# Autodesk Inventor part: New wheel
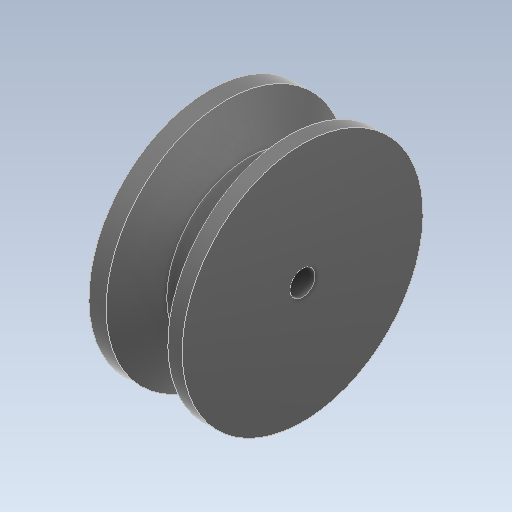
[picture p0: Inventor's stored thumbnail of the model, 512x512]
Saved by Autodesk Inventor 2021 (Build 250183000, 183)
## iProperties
Created: 2021-07
Part Number: New wheel
Material: Acetal Resin, Black
Document SubType Name: Sheet Metal
Designer: user
Density: 1.425 g/cm^3
Sheet Metal Rule: Default_mm
Appearance: Smooth - Black
Author: user
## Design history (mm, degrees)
sketch "Sketch1"
  geometry: L1 (0, 0)-(0, 1.5); L2 (0, 1.5)-(-0.178, 1.5); L3 (-0.178, 1.5)-(-0.482, 1.009); L4 (-0.482, 1.009)-(-0.448, 0); L5 (-0.448, 0)-(0, 0); L6 (-0.178, 1.5)-(-0.178, 0); L7 (-0.482, 1.009)-(0, 1.009); L8 (-0.482, 1.009)-(-0.682, 1.009); L9 (-0.682, 1.009)-(-0.966, 1.009); L10 (-0.966, 1.009)-(-1.161, 1.009); L11 (-1.161, 1.009)-(-1.161, 1.5); L12 (-1.161, 1.5)-(-0.946, 1.5); L13 (-0.946, 1.5)-(-0.946, 1.009); L14 (-0.946, 1.5)-(-0.682, 1.009); L15 (-1.161, 1.009)-(-1.161, 0); L16 (-1.161, 0)-(-0.946, 0); L17 (-0.946, 0)-(-0.946, 1.009); L18 (-0.682, 1.009)-(-0.682, 0); L19 (-0.682, 0)-(-0.946, 0); L20 (-0.682, 0)-(-0.448, 0); L21 (-0.682, 1.009)-(-0.482, 1.009)
  constraints: 42 end point, 8 perpendicular, 7 point on line, 4 horizontal, 2 vertical, 1 parallel
  dimensions: "d0" = 1.5 distance of L1.start L1.end; "d1" = 0.2 distance of L3.end L8.end
revolve "Revolution1" sketch "Sketch1" stored, may be unused: angle "d2" = 90 deg
sketch "Sketch2"
  geometry: C1 r 0.155 at (0, 0); 1 further point
  constraints: 1 centre point, 1 coincident
  dimensions: "d3" = 0.31 diameter of C1
cut "Cut1" sketch "Sketch2" dims "d5" = 0.5 (= Thickness), "d6" = 0
body "Solid1"
other parameters: "Thickness" = 0.5, "BendRadius" = 0.5 (= Thickness), "BendReliefWidth" = 0.5 (= Thickness), "BendReliefDepth" = 0.25 (= 0.5 x Thickness), "CornerReliefSize" = 2 (= 4 x Thickness), "SeamGap" = 0.01, "MinimumRemnant" = 1 (= 2 x Thickness), "TransitionRadius" = 0.5 (= BendRadius), "JacobiRadiusSize" = 0.5 (= BendRadius), "GapSize" = 0.5 (= Thickness), "d4" = 0.5 (= Thickness)
